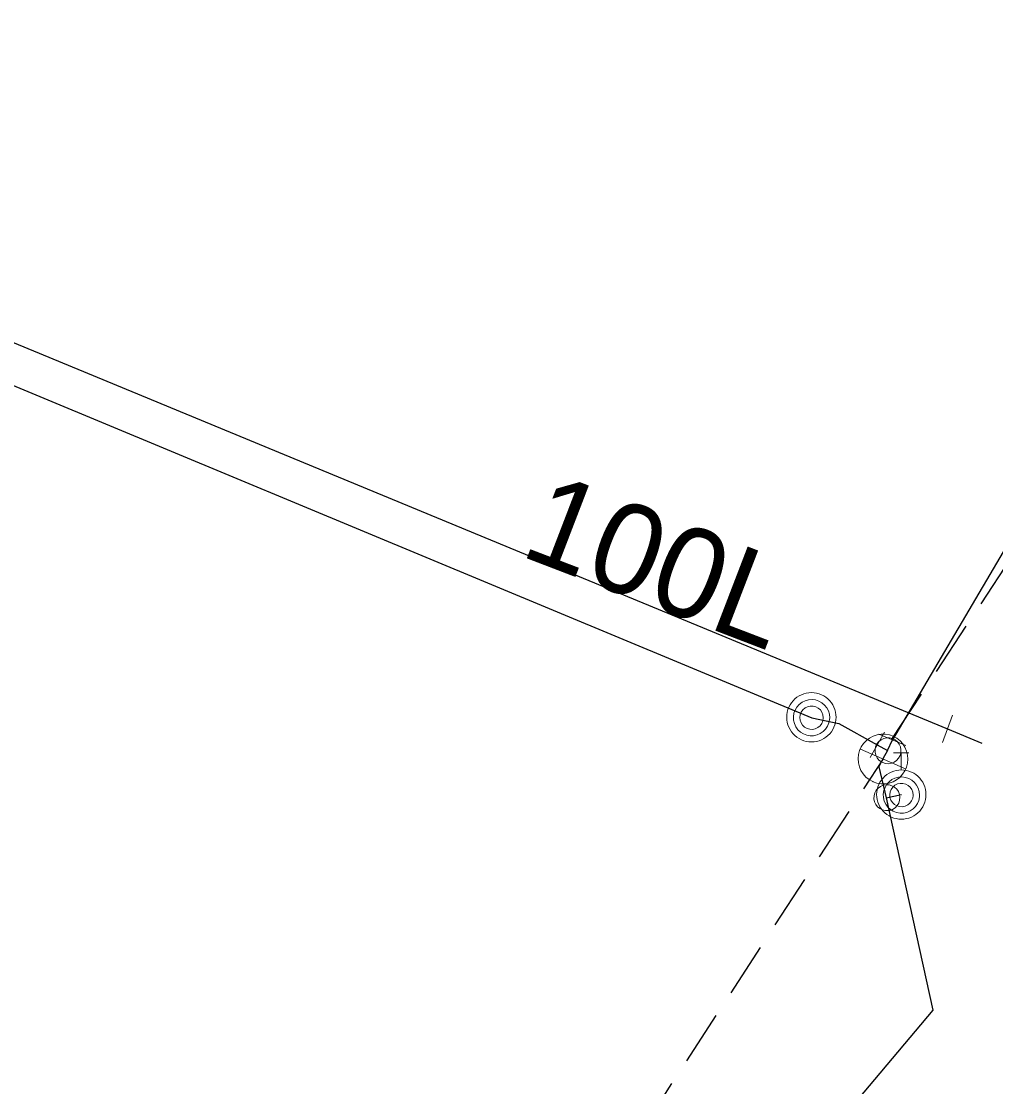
# Model space of a CAD drawing. Extents: x -735085 to -733500, y -1044153 to -1043402.
# Drawn here: x -734690.58 to -734673.3, y -1043590.44 to -1043571.53 of the extents above; entities that cross this region are included whole.
import ezdxf

# ---------------------------------------------------------------- set-up
doc = ezdxf.new("R2010")
doc.units = 0
doc.header["$LTSCALE"] = 0.32
doc.linetypes.add('MEDIUM_DASHED', pattern=[4.5, 3, -1.5])
doc.layers.add('15', color=7, linetype='Continuous')
doc.layers.add('8', color=7, linetype='Continuous', lineweight=13)

msp = doc.modelspace()

# ---------------------------------------------------------------- linework, layer by layer
at = {"layer": '8', "linetype": 'MEDIUM_DASHED', "lineweight": 25}
msp.add_line((-734675.14, -1043584.27), (-734671.028, -1043578.02), dxfattribs=at)
at = {"layer": '8'}
for p, q in [((-734674.061, -1043583.842), (-734674.241, -1043584.327)), ((-734675.272, -1043584.143), (-734675.524, -1043584.594)), ((-734675.368, -1043584.179), (-734674.891, -1043584.379)), ((-734675.696, -1043584.445), (-734674.896, -1043584.795)), ((-734675.109, -1043584.513), (-734674.839, -1043584.513)), ((-734674.974, -1043584.814), (-734674.974, -1043584.516))]:
    msp.add_line(p, q, dxfattribs=at)
at = {"layer": '8', "lineweight": 25}
for p, q in [((-734674.151, -1043584.087), (-734673.545, -1043584.338)), ((-734675.219, -1043584.47), (-734675.3, -1043584.62)), ((-734675.239, -1043585.31), (-734674.969, -1043585.25))]:
    msp.add_line(p, q, dxfattribs=at)
for points in [[(-734792.71, -1043535.18), (-734782.352, -1043539.852), (-734773.644, -1043543.536), (-734767.807, -1043545.587), (-734738.734, -1043557.836), (-734732.528, -1043560.258), (-734709.46, -1043569.477), (-734674.151, -1043584.087)], [(-734737.059, -1043558.35), (-734732.69, -1043560.26), (-734714.53, -1043567.89), (-734709.92, -1043569.78), (-734695.94, -1043575.82), (-734676.559, -1043583.89)], [(-734670.46, -1043575.14), (-734672.359, -1043579.58), (-734675.129, -1043584.28)], [(-734676.559, -1043583.89), (-734676.079, -1043583.99), (-734675.399, -1043584.37)], [(-734675.399, -1043584.37), (-734675.219, -1043584.47), (-734675.129, -1043584.28)], [(-734675.3, -1043584.62), (-734675.37, -1043584.76), (-734675.239, -1043585.31)], [(-734675.239, -1043585.31), (-734674.41, -1043589.08), (-734681.719, -1043597.77), (-734686.55, -1043607.43), (-734686.98, -1043608.45)]]:
    msp.add_lwpolyline(points, dxfattribs=at)
at = {"layer": '8'}
for points in [[(-734676.129, -1043583.879), (-734676.131, -1043583.834), (-734676.138, -1043583.789), (-734676.15, -1043583.744), (-734676.166, -1043583.702), (-734676.187, -1043583.661), (-734676.212, -1043583.622), (-734676.241, -1043583.587), (-734676.273, -1043583.554), (-734676.309, -1043583.526), (-734676.347, -1043583.501), (-734676.388, -1043583.48), (-734676.431, -1043583.463), (-734676.475, -1043583.451), (-734676.52, -1043583.444), (-734676.566, -1043583.442), (-734676.612, -1043583.444), (-734676.657, -1043583.451), (-734676.701, -1043583.463), (-734676.744, -1043583.48), (-734676.785, -1043583.501), (-734676.823, -1043583.526), (-734676.859, -1043583.554), (-734676.891, -1043583.587), (-734676.92, -1043583.622), (-734676.945, -1043583.661), (-734676.966, -1043583.702), (-734676.982, -1043583.744), (-734676.994, -1043583.789), (-734677.001, -1043583.834), (-734677.004, -1043583.88), (-734677.001, -1043583.925), (-734676.994, -1043583.97), (-734676.982, -1043584.015), (-734676.966, -1043584.057), (-734676.945, -1043584.098), (-734676.92, -1043584.137), (-734676.891, -1043584.172), (-734676.859, -1043584.205), (-734676.823, -1043584.233), (-734676.785, -1043584.258), (-734676.744, -1043584.279), (-734676.701, -1043584.296), (-734676.657, -1043584.307), (-734676.612, -1043584.315), (-734676.566, -1043584.317), (-734676.52, -1043584.315), (-734676.475, -1043584.307), (-734676.431, -1043584.296), (-734676.388, -1043584.279), (-734676.347, -1043584.258), (-734676.309, -1043584.233), (-734676.273, -1043584.205), (-734676.241, -1043584.172), (-734676.212, -1043584.137), (-734676.187, -1043584.098), (-734676.166, -1043584.057), (-734676.15, -1043584.015), (-734676.138, -1043583.97), (-734676.131, -1043583.925), (-734676.129, -1043583.88)], [(-734674.534, -1043585.251), (-734674.536, -1043585.206), (-734674.543, -1043585.161), (-734674.555, -1043585.116), (-734674.571, -1043585.074), (-734674.592, -1043585.033), (-734674.617, -1043584.994), (-734674.646, -1043584.959), (-734674.678, -1043584.926), (-734674.714, -1043584.898), (-734674.752, -1043584.873), (-734674.793, -1043584.852), (-734674.836, -1043584.835), (-734674.88, -1043584.823), (-734674.925, -1043584.816), (-734674.971, -1043584.814), (-734675.017, -1043584.816), (-734675.062, -1043584.823), (-734675.106, -1043584.835), (-734675.149, -1043584.852), (-734675.19, -1043584.873), (-734675.228, -1043584.898), (-734675.264, -1043584.926), (-734675.296, -1043584.959), (-734675.325, -1043584.994), (-734675.35, -1043585.033), (-734675.371, -1043585.074), (-734675.387, -1043585.116), (-734675.399, -1043585.161), (-734675.406, -1043585.206), (-734675.409, -1043585.252), (-734675.406, -1043585.297), (-734675.399, -1043585.342), (-734675.387, -1043585.387), (-734675.371, -1043585.429), (-734675.35, -1043585.47), (-734675.325, -1043585.509), (-734675.296, -1043585.544), (-734675.264, -1043585.577), (-734675.228, -1043585.605), (-734675.19, -1043585.63), (-734675.149, -1043585.651), (-734675.106, -1043585.668), (-734675.062, -1043585.679), (-734675.017, -1043585.687), (-734674.971, -1043585.689), (-734674.925, -1043585.687), (-734674.88, -1043585.679), (-734674.836, -1043585.668), (-734674.793, -1043585.651), (-734674.752, -1043585.63), (-734674.714, -1043585.605), (-734674.678, -1043585.577), (-734674.646, -1043585.544), (-734674.617, -1043585.509), (-734674.592, -1043585.47), (-734674.571, -1043585.429), (-734674.555, -1043585.387), (-734674.543, -1043585.342), (-734674.536, -1043585.297), (-734674.534, -1043585.252)]]:
    msp.add_lwpolyline(points, dxfattribs=at)
for points in [[(-734676.242, -1043583.887), (-734676.248, -1043583.826), (-734676.266, -1043583.766), (-734676.295, -1043583.711), (-734676.334, -1043583.663), (-734676.381, -1043583.623), (-734676.435, -1043583.593), (-734676.494, -1043583.573), (-734676.556, -1043583.566), (-734676.618, -1043583.57), (-734676.678, -1043583.586), (-734676.733, -1043583.614), (-734676.783, -1043583.651), (-734676.824, -1043583.698), (-734676.856, -1043583.751), (-734676.876, -1043583.81), (-734676.886, -1043583.871), (-734676.883, -1043583.933), (-734676.868, -1043583.993), (-734676.842, -1043584.05), (-734676.806, -1043584.1), (-734676.76, -1043584.143), (-734676.708, -1043584.175), (-734676.65, -1043584.198), (-734676.589, -1043584.208), (-734676.527, -1043584.207), (-734676.466, -1043584.194), (-734676.409, -1043584.169), (-734676.358, -1043584.134), (-734676.314, -1043584.09), (-734676.28, -1043584.038), (-734676.256, -1043583.981), (-734676.244, -1043583.92)], [(-734676.356, -1043583.887), (-734676.362, -1043583.838), (-734676.379, -1043583.791), (-734676.407, -1043583.75), (-734676.445, -1043583.717), (-734676.489, -1043583.693), (-734676.537, -1043583.681), (-734676.587, -1043583.68), (-734676.635, -1043583.692), (-734676.68, -1043583.714), (-734676.718, -1043583.747), (-734676.747, -1043583.787), (-734676.766, -1043583.834), (-734676.773, -1043583.883), (-734676.768, -1043583.933), (-734676.751, -1043583.98), (-734676.724, -1043584.022), (-734676.687, -1043584.056), (-734676.644, -1043584.08), (-734676.596, -1043584.094), (-734676.546, -1043584.095), (-734676.497, -1043584.085), (-734676.452, -1043584.063), (-734676.413, -1043584.031), (-734676.383, -1043583.992), (-734676.364, -1043583.946), (-734676.356, -1043583.896)], [(-734675.473, -1043585.025), (-734675.404, -1043585.049), (-734675.332, -1043585.06), (-734675.259, -1043585.061), (-734675.187, -1043585.048), (-734675.119, -1043585.025), (-734675.055, -1043584.991), (-734674.998, -1043584.946), (-734674.948, -1043584.892), (-734674.908, -1043584.832), (-734674.879, -1043584.765), (-734674.86, -1043584.695), (-734674.855, -1043584.622), (-734674.86, -1043584.55), (-734674.877, -1043584.479), (-734674.907, -1043584.412), (-734674.946, -1043584.352), (-734674.995, -1043584.297), (-734675.052, -1043584.253), (-734675.115, -1043584.218), (-734675.184, -1043584.193), (-734675.256, -1043584.181), (-734675.328, -1043584.18), (-734675.401, -1043584.191), (-734675.47, -1043584.214), (-734675.534, -1043584.248), (-734675.592, -1043584.293), (-734675.642, -1043584.345), (-734675.682, -1043584.406), (-734675.711, -1043584.472), (-734675.73, -1043584.542), (-734675.738, -1043584.614), (-734675.733, -1043584.688), (-734675.716, -1043584.758), (-734675.687, -1043584.825), (-734675.648, -1043584.886), (-734675.6, -1043584.941), (-734675.544, -1043584.986), (-734675.479, -1043585.022)], [(-734675.301, -1043584.685), (-734675.251, -1043584.701), (-734675.198, -1043584.704), (-734675.147, -1043584.696), (-734675.098, -1043584.676), (-734675.055, -1043584.646), (-734675.02, -1043584.606), (-734674.995, -1043584.561), (-734674.98, -1043584.51), (-734674.978, -1043584.458), (-734674.988, -1043584.406), (-734675.01, -1043584.358), (-734675.041, -1043584.316), (-734675.081, -1043584.282), (-734675.128, -1043584.258), (-734675.179, -1043584.245), (-734675.231, -1043584.245), (-734675.282, -1043584.255), (-734675.33, -1043584.278), (-734675.371, -1043584.31), (-734675.404, -1043584.351), (-734675.427, -1043584.398), (-734675.438, -1043584.45), (-734675.438, -1043584.502), (-734675.425, -1043584.554), (-734675.402, -1043584.6), (-734675.368, -1043584.641), (-734675.326, -1043584.672)], [(-734675.175, -1043585.532), (-734675.126, -1043585.514), (-734675.081, -1043585.485), (-734675.045, -1043585.448), (-734675.018, -1043585.402), (-734675.002, -1043585.352), (-734674.998, -1043585.3), (-734675.005, -1043585.248), (-734675.024, -1043585.199), (-734675.053, -1043585.156), (-734675.093, -1043585.12), (-734675.139, -1043585.095), (-734675.188, -1043585.08), (-734675.242, -1043585.077), (-734675.293, -1043585.086), (-734675.342, -1043585.106), (-734675.384, -1043585.137), (-734675.418, -1043585.176), (-734675.443, -1043585.223), (-734675.456, -1043585.274), (-734675.458, -1043585.326), (-734675.448, -1043585.378), (-734675.426, -1043585.426), (-734675.394, -1043585.467), (-734675.353, -1043585.501), (-734675.307, -1043585.524), (-734675.255, -1043585.536), (-734675.203, -1043585.536)], [(-734674.648, -1043585.26), (-734674.654, -1043585.198), (-734674.672, -1043585.139), (-734674.701, -1043585.084), (-734674.739, -1043585.035), (-734674.787, -1043584.995), (-734674.841, -1043584.965), (-734674.9, -1043584.946), (-734674.962, -1043584.938), (-734675.024, -1043584.943), (-734675.084, -1043584.959), (-734675.139, -1043584.986), (-734675.189, -1043585.024), (-734675.23, -1043585.07), (-734675.261, -1043585.124), (-734675.282, -1043585.182), (-734675.291, -1043585.244), (-734675.288, -1043585.306), (-734675.274, -1043585.366), (-734675.248, -1043585.422), (-734675.211, -1043585.473), (-734675.166, -1043585.515), (-734675.114, -1043585.548), (-734675.056, -1043585.57), (-734674.994, -1043585.581), (-734674.932, -1043585.58), (-734674.872, -1043585.567), (-734674.815, -1043585.542), (-734674.763, -1043585.507), (-734674.72, -1043585.463), (-734674.686, -1043585.411), (-734674.662, -1043585.354), (-734674.65, -1043585.293)], [(-734674.761, -1043585.26), (-734674.767, -1043585.211), (-734674.785, -1043585.164), (-734674.813, -1043585.123), (-734674.85, -1043585.089), (-734674.894, -1043585.066), (-734674.943, -1043585.053), (-734674.993, -1043585.053), (-734675.041, -1043585.064), (-734675.086, -1043585.087), (-734675.124, -1043585.119), (-734675.153, -1043585.16), (-734675.171, -1043585.206), (-734675.178, -1043585.256), (-734675.173, -1043585.305), (-734675.157, -1043585.352), (-734675.13, -1043585.394), (-734675.093, -1043585.428), (-734675.05, -1043585.453), (-734675.001, -1043585.466), (-734674.952, -1043585.468), (-734674.903, -1043585.457), (-734674.858, -1043585.436), (-734674.819, -1043585.404), (-734674.789, -1043585.364), (-734674.77, -1043585.318), (-734674.762, -1043585.269)]]:
    msp.add_lwpolyline(points, close=True, dxfattribs=at)
at = {"layer": '8', "linetype": 'MEDIUM_DASHED', "lineweight": 25}
msp.add_lwpolyline([(-734689.96, -1043607.2), (-734689.776, -1043606.875), (-734675.289, -1043584.62)], dxfattribs=at)

# ---------------------------------------------------------------- texts
at = {"layer": '15'}
msp.add_text('100L', height=1.6, rotation=339, dxfattribs=at).set_placement((-734681.767, -1043581.001))

doc.saveas('drawing.dxf')
